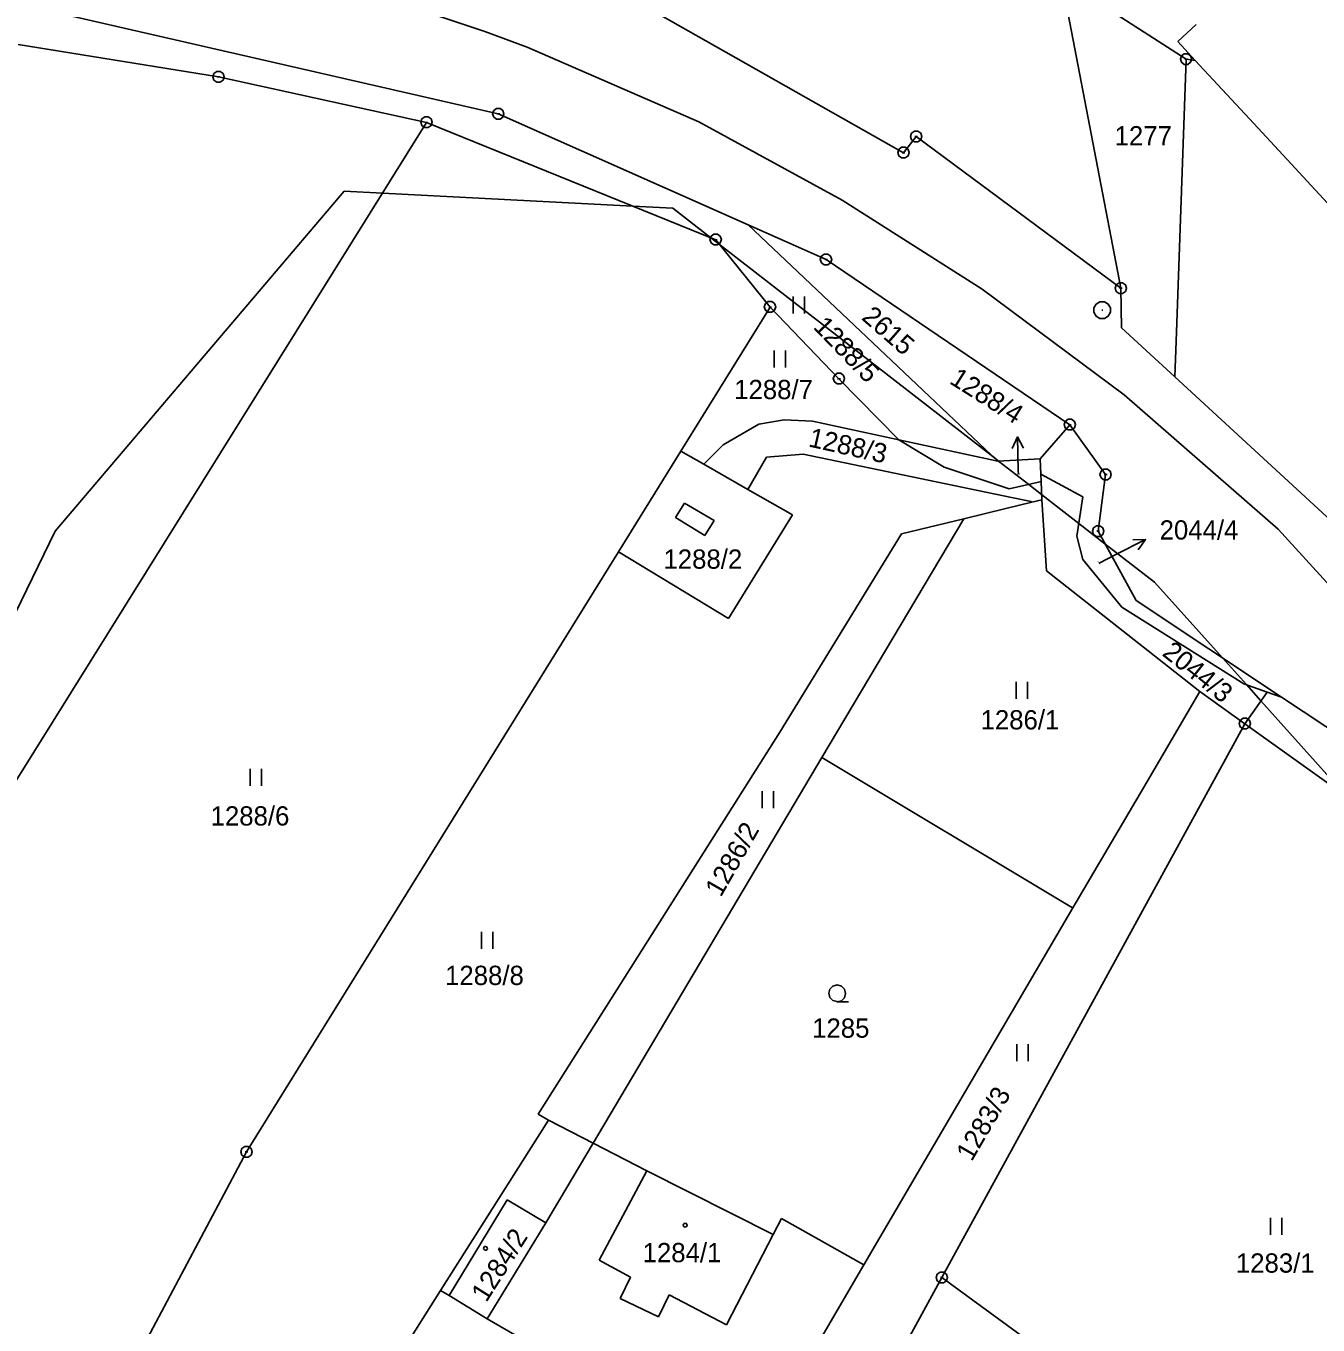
# Model space of a CAD drawing. Extents: x -806774 to -803680, y -1151731 to -1150053.
# Drawn here: x -804318.1 to -804204.1, y -1150598.5 to -1150483.9 of the extents above; entities that cross this region are included whole.
import ezdxf

# ---------------------------------------------------------------- set-up
doc = ezdxf.new("R2010")
doc.units = 0
for name, color, linetype in [('1', 7, 'Continuous'), ('11', 7, 'Continuous'), ('12', 7, 'Continuous'), ('2', 7, 'Continuous'), ('3', 7, 'Continuous'), ('4', 7, 'Continuous'), ('5', 7, 'Continuous'), ('6', 7, 'Continuous'), ('7', 7, 'Continuous'), ('8', 7, 'Continuous')]:
    doc.layers.add(name, color=color, linetype=linetype)

msp = doc.modelspace()

# ---------------------------------------------------------------- linework, layer by layer
at = {"layer": '1'}
for p, q in [((-804240.65, -1150495.11), (-804268.19, -1150479.5)), ((-804215.71, -1150486.85), (-804226.72, -1150479.76)), ((-804226.72, -1150479.76), (-804221.47, -1150507.06)), ((-804317.89, -1150482.17), (-804276.4, -1150491.69)), ((-804214.82, -1150483.78), (-804216.44, -1150485.29)), ((-804318.77, -1150485.56), (-804301.09, -1150488.42)), ((-804216.44, -1150485.29), (-804214.9, -1150486.96)), ((-804215.71, -1150486.85), (-804216.27, -1150502.62)), ((-804215.71, -1150486.85), (-804214.9, -1150486.96)), ((-804214.9, -1150486.96), (-804209.74, -1150492.54)), ((-804301.09, -1150488.42), (-804282.73, -1150492.43)), ((-804282.73, -1150492.43), (-804344.13, -1150590.85)), ((-804282.73, -1150492.43), (-804257.22, -1150502.78)), ((-804276.4, -1150491.69), (-804254.35, -1150501.48)), ((-804209.74, -1150492.54), (-804206.45, -1150496.09)), ((-804239.52, -1150493.68), (-804240.65, -1150495.11)), ((-804221.47, -1150507.06), (-804239.52, -1150493.68)), ((-804206.45, -1150496.09), (-804175.77, -1150529.26)), ((-804254.35, -1150501.48), (-804247.48, -1150504.53)), ((-804232.31, -1150522.31), (-804254.35, -1150501.48)), ((-804257.22, -1150502.78), (-804252.42, -1150508.72)), ((-804216.27, -1150502.62), (-804216.54, -1150510.11)), ((-804247.48, -1150504.53), (-804225.97, -1150519.11)), ((-804221.41, -1150510.55), (-804221.47, -1150507.06)), ((-804252.42, -1150508.72), (-804260.3, -1150521.44)), ((-804252.42, -1150508.72), (-804246.34, -1150515.05)), ((-804221.41, -1150510.55), (-804216.71, -1150514.88)), ((-804216.6, -1150511.73), (-804216.54, -1150510.11)), ((-804216.71, -1150514.88), (-804216.6, -1150511.73)), ((-804241.05, -1150520.43), (-804246.34, -1150515.05)), ((-804216.71, -1150514.88), (-804196.65, -1150533.37)), ((-804256.57, -1150520.87), (-804253.42, -1150519.06)), ((-804253.42, -1150519.06), (-804251.17, -1150518.68)), ((-804251.17, -1150518.68), (-804248.68, -1150518.8)), ((-804248.68, -1150518.8), (-804241.05, -1150520.43)), ((-804228.6, -1150522.11), (-804225.97, -1150519.11)), ((-804222.81, -1150523.51), (-804225.97, -1150519.11)), ((-804258.26, -1150522.6), (-804256.57, -1150520.87)), ((-804241.05, -1150520.43), (-804237.05, -1150522.86)), ((-804232.31, -1150522.31), (-804241.05, -1150520.43)), ((-804265.8, -1150530.32), (-804260.3, -1150521.44)), ((-804260.3, -1150521.44), (-804258.26, -1150522.6)), ((-804254.38, -1150524.81), (-804252.74, -1150521.97)), ((-804252.74, -1150521.97), (-804249.49, -1150521.69)), ((-804231.13, -1150525.52), (-804249.49, -1150521.69)), ((-804232.31, -1150522.31), (-804228.6, -1150522.11)), ((-804228.6, -1150522.11), (-804228.54, -1150523.48)), ((-804258.26, -1150522.6), (-804254.38, -1150524.81)), ((-804237.05, -1150522.86), (-804231.31, -1150524.77)), ((-804228.54, -1150523.48), (-804228.51, -1150524.13)), ((-804228.54, -1150523.48), (-804224.81, -1150525.46)), ((-804222.81, -1150523.51), (-804223.47, -1150528.51)), ((-804254.38, -1150524.81), (-804250.43, -1150527.06)), ((-804231.31, -1150524.77), (-804228.73, -1150524.18)), ((-804228.51, -1150524.13), (-804228.73, -1150524.18)), ((-804228.51, -1150524.13), (-804228.45, -1150525.73)), ((-804231.62, -1150526.5), (-804229.32, -1150525.94)), ((-804229.39, -1150525.88), (-804231.13, -1150525.52)), ((-804229.39, -1150525.88), (-804229.32, -1150525.94)), ((-804229.32, -1150525.94), (-804228.45, -1150525.73)), ((-804228.03, -1150531.99), (-804228.45, -1150525.73)), ((-804224.81, -1150525.46), (-804225.36, -1150528.93)), ((-804250.43, -1150527.06), (-804256.08, -1150536.2)), ((-804235.33, -1150527.4), (-804231.62, -1150526.5)), ((-804235.33, -1150527.4), (-804247.84, -1150548.47)), ((-804240.82, -1150528.74), (-804235.33, -1150527.4)), ((-804251.57, -1150546.24), (-804240.82, -1150528.74)), ((-804225.36, -1150528.93), (-804224.83, -1150531.01)), ((-804223.47, -1150528.51), (-804220.13, -1150534.61)), ((-804265.8, -1150530.32), (-804298.61, -1150583.27)), ((-804256.08, -1150536.2), (-804265.8, -1150530.32)), ((-804224.83, -1150531.01), (-804221.38, -1150535.19)), ((-804214.51, -1150542.63), (-804228.03, -1150531.99)), ((-804220.13, -1150534.61), (-804207.3, -1150543.14)), ((-804221.38, -1150535.19), (-804210.61, -1150541.96)), ((-804210.61, -1150541.96), (-804208.56, -1150542.69)), ((-804219.19, -1150550.65), (-804214.51, -1150542.63)), ((-804210.52, -1150545.49), (-804214.51, -1150542.63)), ((-804210.52, -1150545.49), (-804208.56, -1150542.69)), ((-804208.56, -1150542.69), (-804207.3, -1150543.14)), ((-804196.79, -1150550.13), (-804207.3, -1150543.14)), ((-804251.57, -1150546.24), (-804272.88, -1150579.95)), ((-804237.26, -1150594.36), (-804210.52, -1150545.49)), ((-804210.52, -1150545.49), (-804197.78, -1150554.62)), ((-804247.84, -1150548.47), (-804268.04, -1150582.49)), ((-804247.84, -1150548.47), (-804225.88, -1150561.63)), ((-804225.71, -1150561.73), (-804219.19, -1150550.65)), ((-804244.16, -1150593.22), (-804225.71, -1150561.73)), ((-804225.88, -1150561.63), (-804225.71, -1150561.73)), ((-804271.97, -1150580.46), (-804281.49, -1150595.48)), ((-804271.97, -1150580.46), (-804272.88, -1150579.95)), ((-804271.97, -1150580.46), (-804268.04, -1150582.49)), ((-804298.61, -1150583.27), (-804317.72, -1150619.16)), ((-804272.21, -1150589.52), (-804268.04, -1150582.49)), ((-804263.3, -1150584.93), (-804268.04, -1150582.49)), ((-804252.15, -1150590.56), (-804263.3, -1150584.93)), ((-804277.39, -1150597.99), (-804272.21, -1150589.52)), ((-804252.15, -1150590.56), (-804251.42, -1150589.13)), ((-804251.42, -1150589.13), (-804244.16, -1150593.22)), ((-804252.02, -1150606.69), (-804244.16, -1150593.22)), ((-804237.26, -1150594.36), (-804245.9, -1150610.15)), ((-804220.16, -1150606.83), (-804237.26, -1150594.36)), ((-804281.49, -1150595.48), (-804293.22, -1150613.99)), ((-804281.49, -1150595.48), (-804280.75, -1150595.93)), ((-804280.75, -1150595.93), (-804277.39, -1150597.99)), ((-804277.39, -1150597.99), (-804254.42, -1150611.22))]:
    msp.add_line(p, q, dxfattribs=at)
at = {"layer": '11'}
msp.add_lwpolyline([(-804201.49, -1150551.96), (-804209.11, -1150543.47), (-804210.39, -1150542.04), (-804212.51, -1150539.67), (-804218.5, -1150533), (-804222.87, -1150529.61), (-804225.18, -1150527.81), (-804228.47, -1150525.26), (-804229.6, -1150524.38), (-804232.27, -1150522.31), (-804232.51, -1150522.12), (-804256.88, -1150503.2), (-804257.64, -1150502.61), (-804261, -1150500), (-804264.52, -1150499.82), (-804286.63, -1150498.67), (-804290, -1150498.5), (-804315.5, -1150528.5), (-804325, -1150548), (-804325.91, -1150561.64), (-804327, -1150578), (-804320.5, -1150605)], dxfattribs=at)
at = {"layer": '12'}
for p, q in [((-804214.82, -1150483.78), (-804216.44, -1150485.29)), ((-804216.44, -1150485.29), (-804214.9, -1150486.96)), ((-804214.9, -1150486.96), (-804209.74, -1150492.54)), ((-804209.74, -1150492.54), (-804206.45, -1150496.09)), ((-804206.45, -1150496.09), (-804175.77, -1150529.26)), ((-804263.3, -1150584.93), (-804267.51, -1150592.83)), ((-804252.15, -1150590.56), (-804263.3, -1150584.93)), ((-804275.61, -1150587.5), (-804280.75, -1150595.93)), ((-804275.61, -1150587.5), (-804272.21, -1150589.52)), ((-804277.39, -1150597.99), (-804272.21, -1150589.52)), ((-804256.28, -1150598.52), (-804252.15, -1150590.56)), ((-804267.51, -1150592.83), (-804264.74, -1150594.31)), ((-804264.74, -1150594.31), (-804265.64, -1150596.2)), ((-804262.27, -1150597.81), (-804261.34, -1150595.87)), ((-804261.34, -1150595.87), (-804256.28, -1150598.52)), ((-804280.75, -1150595.93), (-804277.39, -1150597.99)), ((-804265.64, -1150596.2), (-804262.27, -1150597.81))]:
    msp.add_line(p, q, dxfattribs=at)
at = {"layer": '3'}
for p, q in [((-804250.37, -1150507.8), (-804250.37, -1150509.3)), ((-804249.37, -1150509.3), (-804249.37, -1150507.8)), ((-804252.05, -1150512.57), (-804252.05, -1150514.07)), ((-804251.05, -1150514.07), (-804251.05, -1150512.57)), ((-804230.72, -1150541.79), (-804230.72, -1150543.29)), ((-804229.72, -1150543.29), (-804229.72, -1150541.79)), ((-804298.29, -1150549.47), (-804298.29, -1150550.97)), ((-804297.29, -1150550.97), (-804297.29, -1150549.47)), ((-804253.11, -1150551.44), (-804253.11, -1150552.94)), ((-804252.11, -1150552.94), (-804252.11, -1150551.44)), ((-804277.89, -1150563.86), (-804277.89, -1150565.36)), ((-804276.89, -1150565.36), (-804276.89, -1150563.86)), ((-804230.66, -1150573.77), (-804230.66, -1150575.27)), ((-804229.66, -1150575.27), (-804229.66, -1150573.77)), ((-804208.27, -1150589.08), (-804208.27, -1150590.58)), ((-804207.27, -1150590.58), (-804207.27, -1150589.08))]:
    msp.add_line(p, q, dxfattribs=at)
msp.add_lwpolyline([(-804246.49, -1150570.01), (-804246.87, -1150569.91), (-804247.14, -1150569.64), (-804247.24, -1150569.27), (-804247.14, -1150568.9), (-804246.87, -1150568.63), (-804246.5, -1150568.53), (-804246.13, -1150568.63), (-804245.86, -1150568.9), (-804245.76, -1150569.28), (-804245.86, -1150569.66), (-804246.13, -1150569.93), (-804246.51, -1150570.03), (-804245.51, -1150570.03)], dxfattribs=at)
at = {"layer": '4'}
for p, q in [((-804260.76, -1150527.29), (-804259.98, -1150526.02)), ((-804259.98, -1150526.02), (-804257.34, -1150527.57)), ((-804258.17, -1150528.89), (-804260.76, -1150527.29)), ((-804257.34, -1150527.57), (-804258.17, -1150528.89)), ((-804263.3, -1150584.93), (-804267.51, -1150592.83)), ((-804275.61, -1150587.5), (-804280.75, -1150595.93)), ((-804275.61, -1150587.5), (-804272.21, -1150589.52)), ((-804256.28, -1150598.52), (-804252.15, -1150590.56)), ((-804267.51, -1150592.83), (-804264.74, -1150594.31)), ((-804264.74, -1150594.31), (-804265.64, -1150596.2)), ((-804262.27, -1150597.81), (-804261.34, -1150595.87)), ((-804261.34, -1150595.87), (-804256.28, -1150598.52)), ((-804265.64, -1150596.2), (-804262.27, -1150597.81))]:
    msp.add_line(p, q, dxfattribs=at)
at = {"layer": '5'}
for points in [[(-804259.92, -1150589.56), (-804259.82, -1150589.58), (-804259.77, -1150589.67), (-804259.75, -1150589.73), (-804259.77, -1150589.82), (-804259.85, -1150589.89), (-804259.92, -1150589.9), (-804260.01, -1150589.87), (-804260.07, -1150589.81), (-804260.09, -1150589.73), (-804260.07, -1150589.64), (-804259.99, -1150589.57)], [(-804277.54, -1150591.61), (-804277.44, -1150591.63), (-804277.39, -1150591.72), (-804277.37, -1150591.78), (-804277.39, -1150591.87), (-804277.47, -1150591.94), (-804277.54, -1150591.95), (-804277.63, -1150591.92), (-804277.69, -1150591.86), (-804277.71, -1150591.78), (-804277.69, -1150591.69), (-804277.61, -1150591.62)]]:
    msp.add_lwpolyline(points, close=True, dxfattribs=at)
at = {"layer": '6'}
for p, q in [((-804292.47, -1150479.43), (-804277.59, -1150484.41)), ((-804277.59, -1150484.41), (-804273.85, -1150485.8)), ((-804273.85, -1150485.8), (-804258.72, -1150492.38)), ((-804258.72, -1150492.38), (-804246.07, -1150499.28)), ((-804246.07, -1150499.28), (-804233.7, -1150507.16)), ((-804233.7, -1150507.16), (-804221.19, -1150516.47)), ((-804221.19, -1150516.47), (-804207.6, -1150528.32)), ((-804207.6, -1150528.32), (-804189.79, -1150547.87))]:
    msp.add_line(p, q, dxfattribs=at)
at = {"layer": '7'}
for p, q in [((-804230.59, -1150520.18), (-804230.52, -1150523.18)), ((-804230.51, -1150523.46), (-804230.52, -1150523.18)), ((-804219.29, -1150529.24), (-804221.96, -1150530.6)), ((-804223.38, -1150531.32), (-804221.96, -1150530.6))]:
    msp.add_line(p, q, dxfattribs=at)
for points in [[(-804231.07, -1150521.19), (-804230.59, -1150520.18), (-804230.07, -1150521.17)], [(-804220.4, -1150529.25), (-804219.29, -1150529.24), (-804219.95, -1150530.14)]]:
    msp.add_lwpolyline(points, dxfattribs=at)
at = {"layer": '8'}
for p, q in [((-804215.83, -1150486.85), (-804215.59, -1150486.85)), ((-804301.21, -1150488.42), (-804300.97, -1150488.42)), ((-804282.85, -1150492.43), (-804282.61, -1150492.43)), ((-804276.52, -1150491.69), (-804276.28, -1150491.69)), ((-804239.64, -1150493.68), (-804239.4, -1150493.68)), ((-804240.77, -1150495.11), (-804240.53, -1150495.11)), ((-804257.34, -1150502.78), (-804257.1, -1150502.78)), ((-804247.6, -1150504.53), (-804247.36, -1150504.53)), ((-804221.59, -1150507.06), (-804221.35, -1150507.06)), ((-804252.54, -1150508.72), (-804252.3, -1150508.72)), ((-804223.16, -1150508.99), (-804223.06, -1150508.99)), ((-804246.46, -1150515.05), (-804246.22, -1150515.05)), ((-804226.09, -1150519.11), (-804225.85, -1150519.11)), ((-804222.93, -1150523.51), (-804222.69, -1150523.51)), ((-804223.59, -1150528.51), (-804223.35, -1150528.51)), ((-804210.64, -1150545.49), (-804210.4, -1150545.49)), ((-804298.73, -1150583.27), (-804298.49, -1150583.27)), ((-804237.38, -1150594.36), (-804237.14, -1150594.36))]:
    msp.add_line(p, q, dxfattribs=at)
for points in [[(-804215.56, -1150486.37), (-804215.31, -1150486.55), (-804215.21, -1150486.84), (-804215.31, -1150487.13), (-804215.56, -1150487.31), (-804215.87, -1150487.31), (-804216.12, -1150487.13), (-804216.22, -1150486.84), (-804216.12, -1150486.55), (-804215.87, -1150486.37)], [(-804300.94, -1150487.94), (-804300.69, -1150488.12), (-804300.59, -1150488.41), (-804300.69, -1150488.7), (-804300.94, -1150488.88), (-804301.25, -1150488.88), (-804301.5, -1150488.7), (-804301.6, -1150488.41), (-804301.5, -1150488.12), (-804301.25, -1150487.94)], [(-804276.25, -1150491.21), (-804276, -1150491.39), (-804275.9, -1150491.68), (-804276, -1150491.97), (-804276.25, -1150492.15), (-804276.56, -1150492.15), (-804276.81, -1150491.97), (-804276.91, -1150491.68), (-804276.81, -1150491.39), (-804276.56, -1150491.21)], [(-804282.58, -1150491.95), (-804282.33, -1150492.13), (-804282.23, -1150492.42), (-804282.33, -1150492.71), (-804282.58, -1150492.89), (-804282.89, -1150492.89), (-804283.14, -1150492.71), (-804283.24, -1150492.42), (-804283.14, -1150492.13), (-804282.89, -1150491.95)], [(-804239.37, -1150493.2), (-804239.12, -1150493.38), (-804239.02, -1150493.67), (-804239.12, -1150493.96), (-804239.37, -1150494.14), (-804239.68, -1150494.14), (-804239.93, -1150493.96), (-804240.03, -1150493.67), (-804239.93, -1150493.38), (-804239.68, -1150493.2)], [(-804240.5, -1150494.63), (-804240.25, -1150494.81), (-804240.15, -1150495.1), (-804240.25, -1150495.39), (-804240.5, -1150495.57), (-804240.81, -1150495.57), (-804241.06, -1150495.39), (-804241.16, -1150495.1), (-804241.06, -1150494.81), (-804240.81, -1150494.63)], [(-804257.07, -1150502.3), (-804256.82, -1150502.48), (-804256.72, -1150502.77), (-804256.82, -1150503.06), (-804257.07, -1150503.24), (-804257.38, -1150503.24), (-804257.63, -1150503.06), (-804257.73, -1150502.77), (-804257.63, -1150502.48), (-804257.38, -1150502.3)], [(-804247.33, -1150504.05), (-804247.08, -1150504.23), (-804246.98, -1150504.52), (-804247.08, -1150504.81), (-804247.33, -1150504.99), (-804247.64, -1150504.99), (-804247.89, -1150504.81), (-804247.99, -1150504.52), (-804247.89, -1150504.23), (-804247.64, -1150504.05)], [(-804221.32, -1150506.58), (-804221.07, -1150506.76), (-804220.97, -1150507.05), (-804221.07, -1150507.34), (-804221.32, -1150507.52), (-804221.63, -1150507.52), (-804221.88, -1150507.34), (-804221.98, -1150507.05), (-804221.88, -1150506.76), (-804221.63, -1150506.58)], [(-804252.27, -1150508.24), (-804252.02, -1150508.42), (-804251.92, -1150508.71), (-804252.02, -1150509), (-804252.27, -1150509.18), (-804252.58, -1150509.18), (-804252.83, -1150509), (-804252.93, -1150508.71), (-804252.83, -1150508.42), (-804252.58, -1150508.24)], [(-804222.92, -1150508.27), (-804222.58, -1150508.46), (-804222.39, -1150508.8), (-804222.39, -1150509.19), (-804222.58, -1150509.53), (-804222.92, -1150509.72), (-804223.31, -1150509.72), (-804223.65, -1150509.53), (-804223.84, -1150509.19), (-804223.84, -1150508.8), (-804223.65, -1150508.46), (-804223.31, -1150508.27)], [(-804246.19, -1150514.57), (-804245.94, -1150514.75), (-804245.84, -1150515.04), (-804245.94, -1150515.33), (-804246.19, -1150515.51), (-804246.5, -1150515.51), (-804246.75, -1150515.33), (-804246.85, -1150515.04), (-804246.75, -1150514.75), (-804246.5, -1150514.57)], [(-804225.82, -1150518.63), (-804225.57, -1150518.81), (-804225.47, -1150519.1), (-804225.57, -1150519.39), (-804225.82, -1150519.57), (-804226.13, -1150519.57), (-804226.38, -1150519.39), (-804226.48, -1150519.1), (-804226.38, -1150518.81), (-804226.13, -1150518.63)], [(-804222.66, -1150523.03), (-804222.41, -1150523.21), (-804222.31, -1150523.5), (-804222.41, -1150523.79), (-804222.66, -1150523.97), (-804222.97, -1150523.97), (-804223.22, -1150523.79), (-804223.32, -1150523.5), (-804223.22, -1150523.21), (-804222.97, -1150523.03)], [(-804223.32, -1150528.03), (-804223.07, -1150528.21), (-804222.97, -1150528.5), (-804223.07, -1150528.79), (-804223.32, -1150528.97), (-804223.63, -1150528.97), (-804223.88, -1150528.79), (-804223.98, -1150528.5), (-804223.88, -1150528.21), (-804223.63, -1150528.03)], [(-804210.37, -1150545.01), (-804210.12, -1150545.19), (-804210.02, -1150545.48), (-804210.12, -1150545.77), (-804210.37, -1150545.95), (-804210.68, -1150545.95), (-804210.93, -1150545.77), (-804211.03, -1150545.48), (-804210.93, -1150545.19), (-804210.68, -1150545.01)], [(-804298.46, -1150582.79), (-804298.21, -1150582.97), (-804298.11, -1150583.26), (-804298.21, -1150583.55), (-804298.46, -1150583.73), (-804298.77, -1150583.73), (-804299.02, -1150583.55), (-804299.12, -1150583.26), (-804299.02, -1150582.97), (-804298.77, -1150582.79)], [(-804237.11, -1150593.88), (-804236.86, -1150594.06), (-804236.76, -1150594.35), (-804236.86, -1150594.64), (-804237.11, -1150594.82), (-804237.42, -1150594.82), (-804237.67, -1150594.64), (-804237.77, -1150594.35), (-804237.67, -1150594.06), (-804237.42, -1150593.88)]]:
    msp.add_lwpolyline(points, close=True, dxfattribs=at)

# ---------------------------------------------------------------- texts
at = {"layer": '2'}
for s, height, p in [('1277', 1.7, (-804222.02, -1150494.46)), ('1288/7', 1.7, (-804255.59, -1150516.85)), ('1288/4', 0.1, (-804230.74, -1150523.51)), ('1288/2', 1.7, (-804261.83, -1150531.81)), ('1286/1', 1.7, (-804233.85, -1150545.99)), ('1288/6', 1.7, (-804301.79, -1150554.47)), ('1288/8', 1.7, (-804281.1, -1150568.54)), ('1285', 1.7, (-804248.71, -1150573.19)), ('1284/1', 1.7, (-804263.67, -1150593)), ('1283/1', 1.7, (-804211.32, -1150593.92))]:
    msp.add_text(s, height=height, dxfattribs=at).set_placement(p)
for s, height, rotation, p in [('2615', 1.7, 318.9083, (-804244.43, -1150509.76)), ('1288/5', 1.7, 314.0955, (-804248.69, -1150510.54)), ('1288/3', 1.7, 347.3843, (-804249.11, -1150521.01)), ('2044/4', 0.1, 303.3239, (-804223.56, -1150531.14)), ('2044/3', 1.7, 321.3147, (-804217.91, -1150539.4)), ('1286/2', 1.7, 60.2752, (-804256.77, -1150560.86)), ('1283/3', 1.7, 59.7595, (-804234.63, -1150584.18)), ('1284/2', 1.7, 57.5823, (-804277.46, -1150596.61))]:
    msp.add_text(s, height=height, rotation=rotation, dxfattribs=at).set_placement(p)
at = {"layer": '7'}
msp.add_text('1288/4', height=1.7, rotation=327.8465, dxfattribs=at).set_placement((-804236.68, -1150515.41))
msp.add_text('2044/4', height=1.7, dxfattribs=at).set_placement((-804218.05, -1150529.24))

doc.saveas('drawing.dxf')
